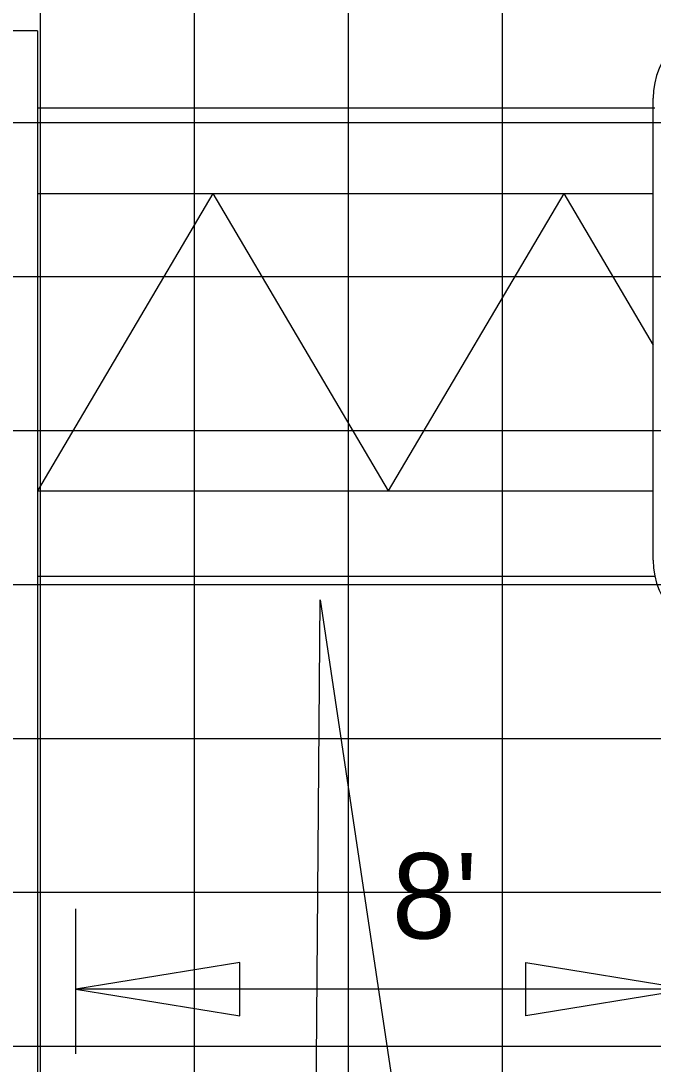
# Model space of a CAD drawing. Extents: x 2193008 to 2198143, y 1236112 to 1237864.
# Drawn here: x 2195346.38 to 2195354.59, y 1237287.87 to 1237301.43 of the extents above; entities that cross this region are included whole.
import ezdxf

# ---------------------------------------------------------------- set-up
doc = ezdxf.new("R2010")
doc.units = 0
for name, color, linetype in [('3', 7, 'Continuous'), ('GSCOLORFILL', 7, 'Continuous'), ('GSDIMS', 7, 'Continuous'), ('Level 55', 7, 'Continuous'), ('Level 62', 7, 'Continuous'), ('M-ROADS', 7, 'Continuous')]:
    doc.layers.add(name, color=color, linetype=linetype)

msp = doc.modelspace()

# ---------------------------------------------------------------- linework, layer by layer
at = {"layer": '3'}
for p, q in [((2195346.592, 1237301.295), (2195346.592, 1237287.538)), ((2195347.092, 1237288.007), (2195347.092, 1237289.893))]:
    msp.add_line(p, q, dxfattribs=at)
at = {"layer": 'GSCOLORFILL'}
msp.add_line((2195354.59, 1237294.42), (2195354.59, 1237300.42), dxfattribs=at)
for centre, start, end in [((2195355.59, 1237300.42), 90, 180), ((2195355.59, 1237294.42), 180, 270)]:
    msp.add_arc(centre, 1, start, end, dxfattribs=at)
at = {"layer": 'GSDIMS'}
for p, q in [((2195346.592, 1237301.295), (2195345.592, 1237301.295)), ((2195346.592, 1237300.295), (2195354.612, 1237300.295)), ((2195348.871, 1237299.184), (2195346.592, 1237295.322)), ((2195346.592, 1237299.184), (2195354.59, 1237299.184)), ((2195348.871, 1237299.184), (2195351.149, 1237295.322)), ((2195353.428, 1237299.184), (2195351.149, 1237295.322)), ((2195353.428, 1237299.184), (2195354.59, 1237297.214)), ((2195346.592, 1237295.322), (2195354.59, 1237295.322)), ((2195346.592, 1237294.211), (2195354.612, 1237294.211)), ((2195355.064, 1237288.848), (2195347.092, 1237288.848))]:
    msp.add_line(p, q, dxfattribs=at)
for points in [[(2195347.092, 1237288.848), (2195349.22, 1237288.501), (2195349.22, 1237289.195)], [(2195355.064, 1237288.848), (2195352.936, 1237288.501), (2195352.936, 1237289.195)]]:
    msp.add_lwpolyline(points, close=True, dxfattribs=at)
at = {"layer": 'Level 62'}
for p, q in [((2195346.632, 1237258.106), (2195346.632, 1237318.106)), ((2195348.632, 1237258.106), (2195348.632, 1237318.106)), ((2195350.632, 1237258.106), (2195350.632, 1237318.106)), ((2195352.632, 1237258.106), (2195352.632, 1237318.106)), ((2195328.632, 1237300.106), (2195448.632, 1237300.106)), ((2195328.632, 1237298.106), (2195448.632, 1237298.106)), ((2195328.632, 1237296.106), (2195448.632, 1237296.106)), ((2195328.632, 1237294.106), (2195448.632, 1237294.106)), ((2195328.632, 1237292.106), (2195448.632, 1237292.106)), ((2195328.632, 1237290.106), (2195448.632, 1237290.106)), ((2195328.632, 1237288.106), (2195448.632, 1237288.106))]:
    msp.add_line(p, q, dxfattribs=at)
at = {"layer": 'M-ROADS'}
msp.add_lwpolyline([(2195346.372, 1237285.319), (2195346.923, 1237285.247), (2195350.191, 1237284.671), (2195350.266, 1237293.904), (2195351.655, 1237284.607), (2195353.263, 1237273.21), (2195353.402, 1237272.769), (2195353.563, 1237272.32), (2195362.292, 1237271.588), (2195366.19, 1237271.258), (2195370.209, 1237270.993), (2195379.415, 1237270.375)], dxfattribs=at)

# ---------------------------------------------------------------- texts
at = {"layer": 'Level 55'}
msp.add_text("8'", height=1.1105, rotation=360, dxfattribs=at).set_placement((2195351.198, 1237289.505))

doc.saveas('drawing.dxf')
